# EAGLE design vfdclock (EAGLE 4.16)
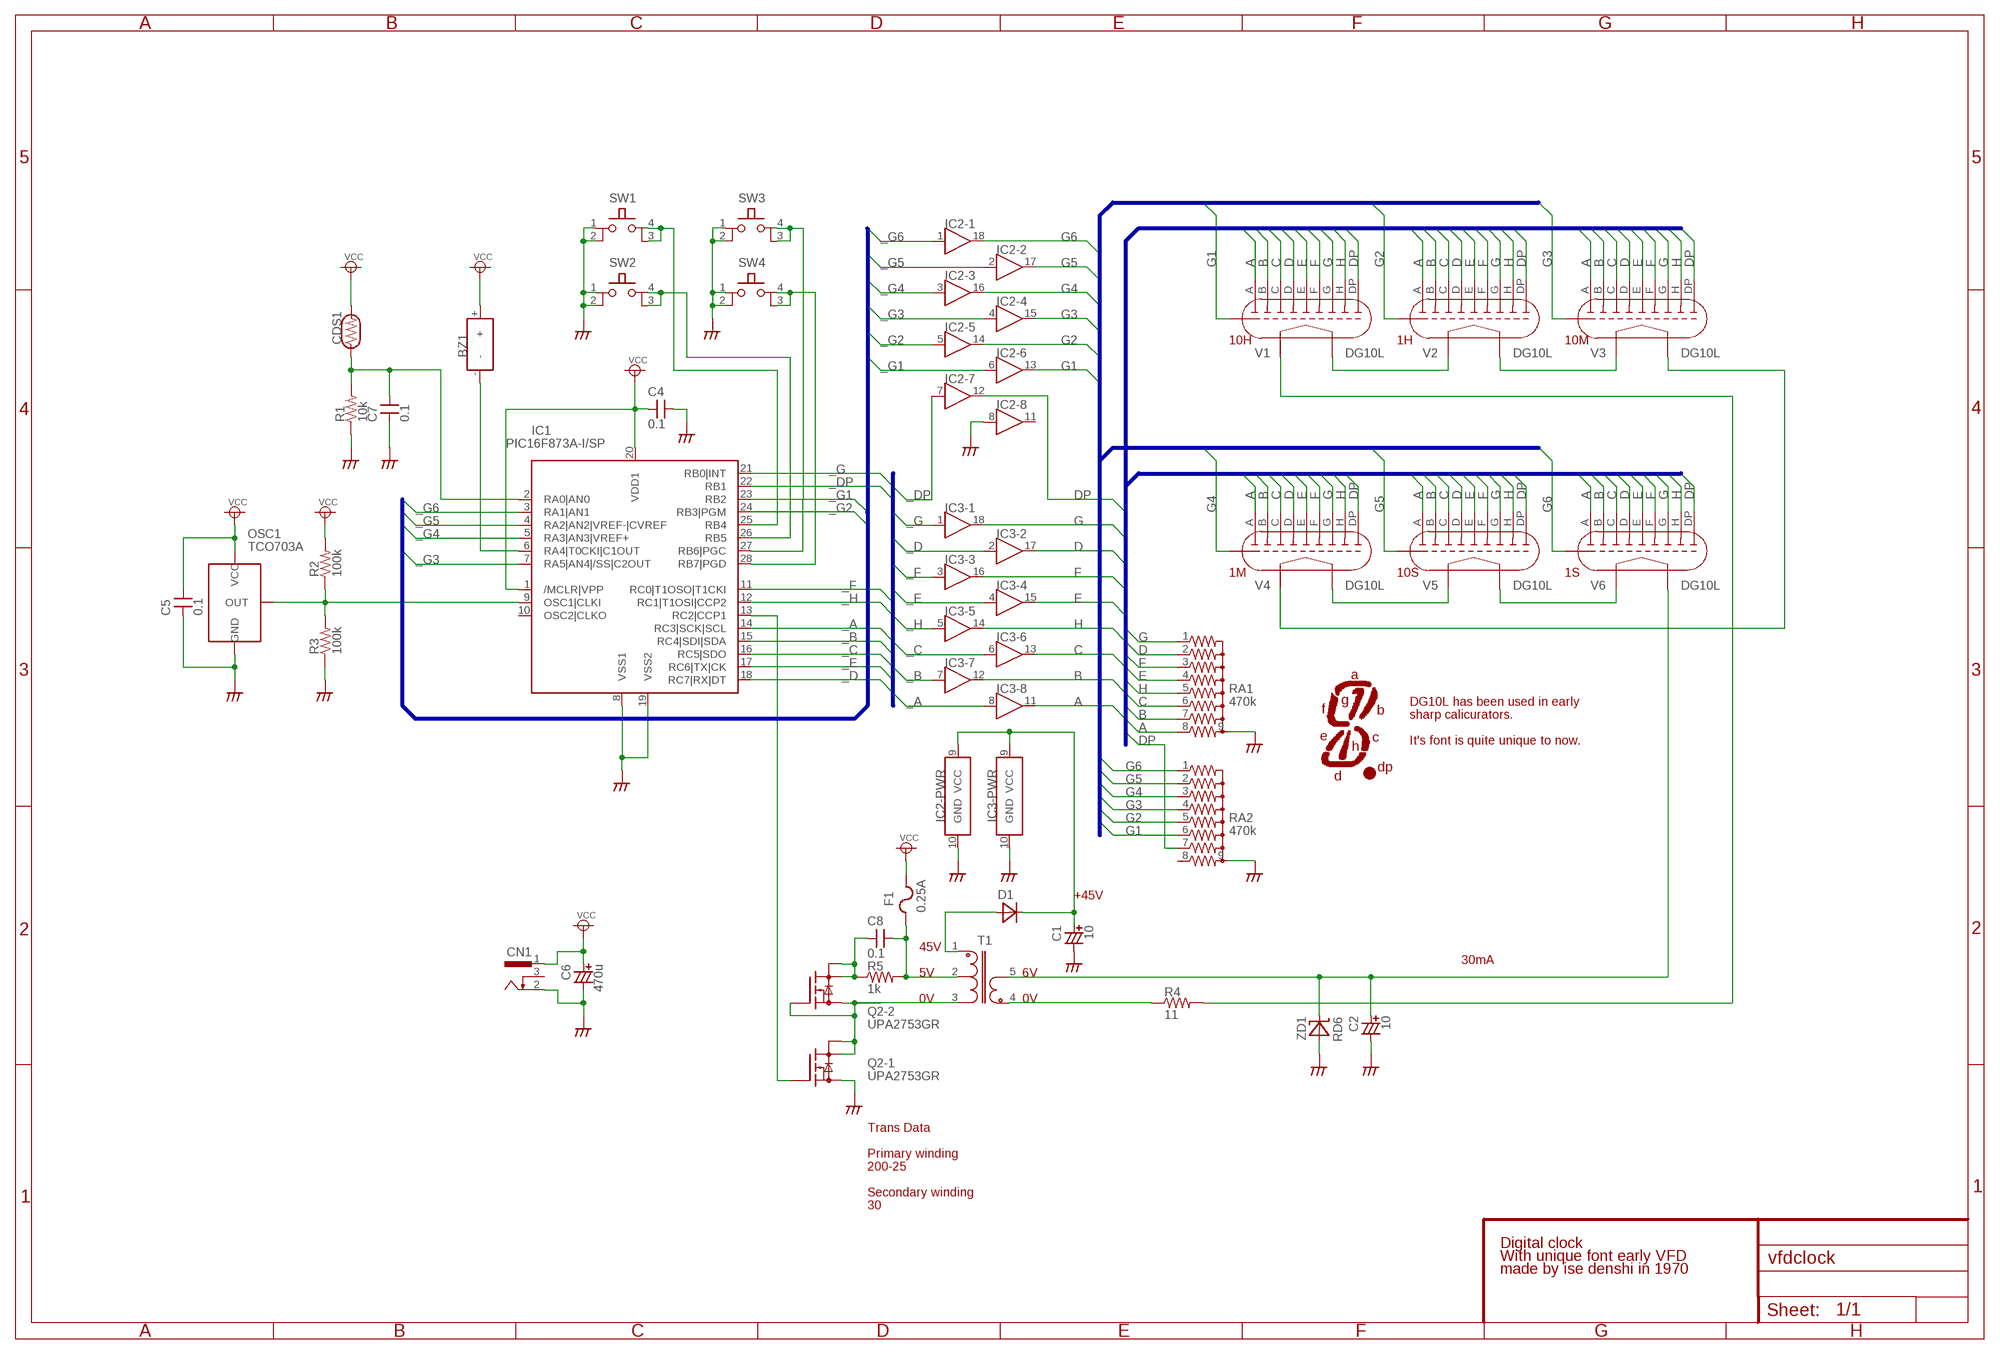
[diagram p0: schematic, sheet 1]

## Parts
BZ1  BUZZER  [HDB06LFPN]
C1  10  CCAP6.5  [CCAP_6.5]
C2  10  CCAP6.5  [CCAP_6.5]
C4  0.1  CAPDIP_2  [CAP_DIP_2]
C5  0.1  CAPDIP_2  [CAP_DIP_2]
C6  470u  CCAP8  [CCAP_8]
C7  0.1  CAPDIP_2  [CAP_DIP_2]
C8  0.1  CAPDIP_2  [CAP_DIP_2]
CDS1  CDS  [CDS_5MM]
CN1  DC-JACK2DC0005D100  [2DC0005D100]
D1  DIODEGENERIC_2  [DIODE_2]
F1  0.25A  POLYSW8X2MM  [AX_08X02_2P_200]
IC1  PIC16F873A-I/SP  [SOCKED-28-3]
IC2  TD62783AP  [SOCKED-18]
IC3  TD62783AP  [SOCKED-18]
OSC1  TCO703A  [TCO703A]
Q2  UPA2753GR  [SOP08]
R1  10k  R0.125W_2P  [R_0.125W_2]
R2  100k  R0.125W_2P  [R_0.125W_2]
R3  100k  R0.125W_2P  [R_0.125W_2]
R4  11  R0.125W_2P  [R_0.125W_2]
R5  1k  R0.125W_2P  [R_0.125W_2]
RA1  470k  R_ARRAY_8  [SIP9]
RA2  470k  R_ARRAY_8  [SIP9]
SW1  PUSHSW-6MM  [PUSHSW-6MM]
SW2  PUSHSW-6MM  [PUSHSW-6MM]
SW3  PUSHSW-6MM  [PUSHSW-6MM]
SW4  PUSHSW-6MM  [PUSHSW-6MM]
T1  TRANS  [TDK_BE16]
V1  DG10L  [DG10L]
V2  DG10L  [DG10L]
V3  DG10L  [DG10L]
V4  DG10L  [DG10L]
V5  DG10L  [DG10L]
V6  DG10L  [DG10L]
ZD1  RD6  ZENER_DIODE  [DIODE_2]

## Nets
_A: IC1.14(RC3|SCK|SCL) IC3.8(-8:IN)
_B: IC1.15(RC4|SDI|SDA) IC3.7(-7:IN)
_C: IC1.16(RC5|SDO) IC3.6(-6:IN)
_D: IC1.18(RC7|RX|DT) IC3.2(-2:IN)
_DP: IC1.22(RB1) IC2.7(-7:IN)
_E: IC1.17(RC6|TX|CK) IC3.4(-4:IN)
_F: IC1.11(RC0|T1OSO|T1CKI) IC3.3(-3:IN)
_G: IC1.21(RB0|INT) IC3.1(-1:IN)
_G1: IC1.23(RB2) IC2.6(-6:IN)
_G2: IC1.24(RB3|PGM) IC2.5(-5:IN)
_G3: IC1.7(RA5|AN4|/SS|C2OUT) IC2.4(-4:IN)
_G4: IC1.5(RA3|AN3|VREF+) IC2.3(-3:IN)
_G5: IC1.4(RA2|AN2|VREF-|CVREF) IC2.2(-2:IN)
_G6: IC1.3(RA1|AN1) IC2.1(-1:IN)
_H: IC1.12(RC1|T1OSI|CCP2) IC3.5(-5:IN)
A: IC3.11(-8:OUT) RA1.8 V1.A V2.A V3.A V4.A V5.A V6.A
B: IC3.12(-7:OUT) RA1.7 V1.B V2.B V3.B V4.B V5.B V6.B
C: IC3.13(-6:OUT) RA1.6 V1.C V2.C V3.C V4.C V5.C V6.C
D: IC3.17(-2:OUT) RA1.2 V1.D V2.D V3.D V4.D V5.D V6.D
DP: IC2.12(-7:OUT) RA2.7 V1.DP V2.DP V3.DP V4.DP V5.DP V6.DP
DVCC: BZ1.+ C4.1 C5.2 C6.+ CDS1.2 CN1.1 F1.2 IC1.1(/MCLR|VPP) IC1.20(VDD1) OSC1.VCC R2.2 ; supply symbol labelled VCC
E: IC3.15(-4:OUT) RA1.4 V1.E V2.E V3.E V4.E V5.E V6.E
F: IC3.16(-3:OUT) RA1.3 V1.F V2.F V3.F V4.F V5.F V6.F
F$1: V1.FL2 V2.FL1
F$2: V2.FL2 V3.FL1
F$3: V3.FL2 V4.FL1
F$4: V4.FL2 V5.FL1
F$5: V5.FL2 V6.FL1
FL1: R4.2 V1.FL1
FL2: C2.+ T1.5(S2) V6.FL2 ZD1.K
G: IC3.18(-1:OUT) RA1.1 V1.G V2.G V3.G V4.G V5.G V6.G
G1: IC2.13(-6:OUT) RA2.6 V1.GRID
G2: IC2.14(-5:OUT) RA2.5 V2.GRID
G3: IC2.15(-4:OUT) RA2.4 V3.GRID
G4: IC2.16(-3:OUT) RA2.3 V4.GRID
G5: IC2.17(-2:OUT) RA2.2 V5.GRID
G6: IC2.18(-1:OUT) RA2.1 V6.GRID
GND: C1.- C2.- C4.2 C5.1 C6.- C7.1 CN1.2 IC1.8(VSS1) IC1.19(VSS2) IC2.8(-8:IN) IC2.10(-PWR:GND) IC3.10(-PWR:GND) OSC1.GND Q2.1(-1:S) R1.1 R3.1 RA1.9(COM) RA2.9(COM) SW1.1 SW1.2 SW2.1 SW2.2 SW3.1 SW3.2 SW4.1 SW4.2 ZD1.A
H: IC3.14(-5:OUT) RA1.5 V1.H V2.H V3.H V4.H V5.H V6.H
N$1: IC1.13(RC2|CCP1) Q2.2(-1:G)
N$2: BZ1.- IC1.6(RA4|T0CKI|C1OUT)
N$3: R4.1 T1.4(S1)
N$4: C1.+ D1.K IC2.9(-PWR:VCC) IC3.9(-PWR:VCC)
N$5: IC1.25(RB4) SW1.3 SW1.4
N$6: IC1.26(RB5) SW2.3 SW2.4
N$7: C8.1 Q2.5(-2:D1) Q2.6(-2:D2) R5.1
N$8: C7.2 CDS1.1 IC1.2(RA0|AN0) R1.2
N$10: D1.A T1.1
N$13: IC1.9(OSC1|CLKI) OSC1.OUT R2.1 R3.2
N$14: C8.2 F1.1 R5.2 T1.2
N$15: Q2.3(-2:S) Q2.4(-2:G) Q2.7(-1:D1) Q2.8(-1:D2) T1.3
N$16: IC1.27(RB6|PGC) SW3.3 SW3.4
N$17: IC1.28(RB7|PGD) SW4.3 SW4.4
Unconnected: CN1.3 IC1.10(OSC2|CLKO) IC2.11(-8:OUT) RA2.8

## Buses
A,B,C,D,E,F,G,H,DP
G[1..6]
_A,_B,_C,_D,_E,_F,_G,_H,_DP
_G[1..6]

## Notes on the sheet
- 10H | 1H | 10M
- 1M | 10S | 1S
- a
- g | DG10L has been used in early
- f | b
- sharp calicurators.
- e | c
- It's font is quite unique to now.
- h
- dp
- d
- +45V
- 45V
- 30mA
- 5V | 6V
- 0V | 0V
- Trans Data
- Primary winding
- 200-25
- Secondary winding
- 30
- Digital clock
- With unique font early VFD
- made by ise denshi in 1970

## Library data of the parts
BZ1 = vfdclock:BUZZER
C1 C2 C6 = vfdclock:CCAP: Polar capacitor
C4 C5 C7 C8 = vfdclock:CAP: Non polar capacitor
CDS1 = vfdclock:CDS
CN1 = vfdclock:DC-JACK
D1 = vfdclock:DIODE
F1 = vfdclock:POLYSW
IC1 = vfdclock:PIC16F873
IC2 IC3 = vfdclock:TD62783
OSC1 = vfdclock:TCO703A
Q2 = vfdclock:UPA2753GR
R1-R5 = vfdclock:R
RA1 RA2 = vfdclock:R_ARRAY_8
SW1-SW4 = vfdclock:PUSHSW-6MM
T1 = vfdclock:TRANS
V1-V6 = vfdclock:DG10L: Early Vacuum Florescent Tube made by ISE denshi. It had unique font with 8 segments. Looks like hand-written number. Official specs are unknown but filament supply is about 0.6V/30mA
ZD1 = vfdclock:ZENER_DIODE

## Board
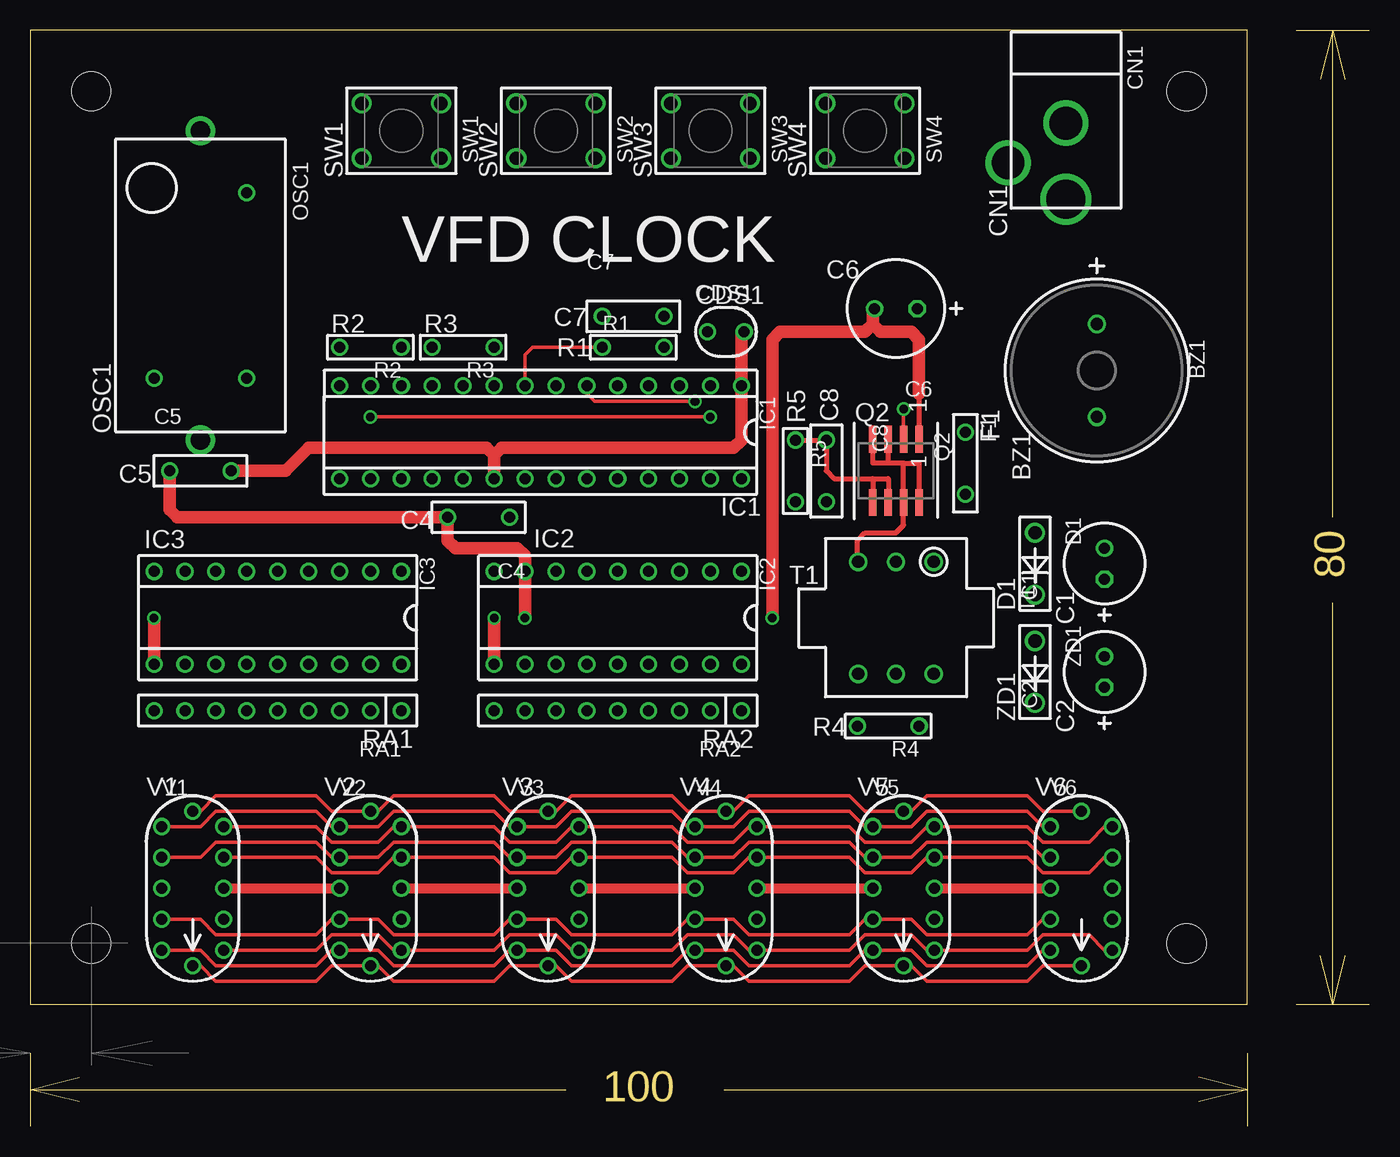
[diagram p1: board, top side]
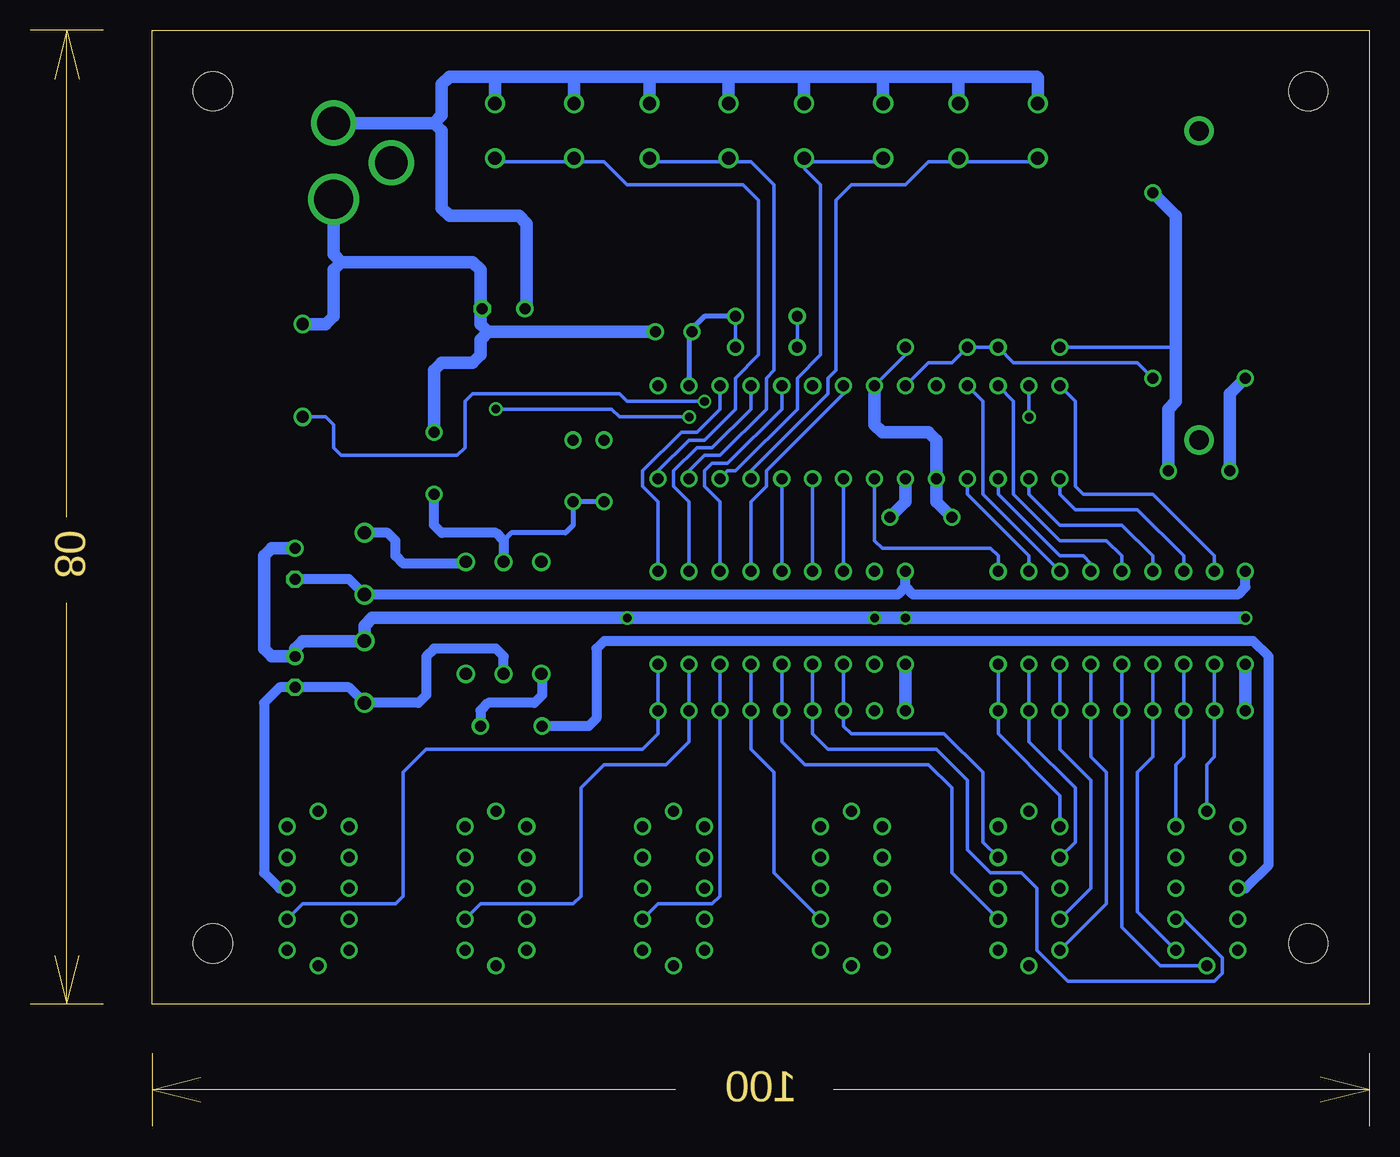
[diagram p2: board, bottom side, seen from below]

Size 110 x 90 mm. Coordinates in mm from the lower left corner, seen from the top.
Outline: 0,6 0,3
Outline: 0,3 0,0
Outline: 100,6 100,3
Outline: 100,3 100,0
Outline: 0,3 44,3
Outline: 57,3 100,3
Outline: 0,3 4,4
Outline: 4,2 0,3
Outline: 100,3 96,4
Outline: 100,3 96,2
Outline: 104,10 107,10
Outline: 107,10 110,10
Outline: 107,10 107,43
Outline: 107,50 107,90
Outline: 104,90 107,90
Outline: 107,90 110,90
Outline: 107,90 106,86
Outline: 107,90 108,86
Outline: 107,10 106,14
Outline: 108,14 107,10
Outline: 0,10 100,10 100,90 0,90 0,10
Copper layers (1*16): Top 0.035mm / dielectric 1.5mm / Bottom 0.035mm
Design rules "Olimex10mils": minimum track width 10mil, minimum drill 0.7mm, track to track 10mil, track to pad 10mil, pad to pad 10mil, via to via 10mil, smd to smd 10mil, copper to edge 40mil, drill to drill 10mil, minimum pad ring 10mil, minimum via ring 8mil, stop-mask expansion 0mil, vias tented up to drill 0mil, thermal gap 10mil
Holes 3.2 mm at 5,85 95,85 95,15 5,15

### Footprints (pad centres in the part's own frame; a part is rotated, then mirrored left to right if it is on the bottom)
HDB06LFPN = drill 1 round: + -3.81,0; - 3.81,0
CCAP_6.5 = drill 0.9 octagon: + -1.27,0 | drill 0.9 round: - 1.27,0
CAP_DIP_2 = drill 0.9 round: 1 -2.54,0; 2 2.54,0
CCAP_8 = drill 0.9 octagon: + -1.75,0 | drill 0.9 round: - 1.75,0
CDS_5MM = drill 0.9 round: 1 -1.5,0; 2 1.5,0
2DC0005D100 = drill 3.2 round: 1 6.25,0 | drill 2.7 round: 2 0,0; 3 3.25,-4.75
DIODE_2 = drill 1.1 round: A -2.54,0; K 2.54,0
AX_08X02_2P_200 = drill 0.9 round: 1 2.54,0; 2 -2.54,0
SOCKED-28-3 = drill 0.9 round: 1 -16.51,-3.81; 2 -13.97,-3.81; 3 -11.43,-3.81; 4 -8.89,-3.81; 5 -6.35,-3.81; 6 -3.81,-3.81; 7 -1.27,-3.81; 8 1.27,-3.81; 9 3.81,-3.81; 10 6.35,-3.81; 11 8.89,-3.81; 12 11.43,-3.81; 13 13.97,-3.81; 14 16.51,-3.81; 15 16.51,3.81; 16 13.97,3.81; 17 11.43,3.81; 18 8.89,3.81; 19 6.35,3.81; 20 3.81,3.81; 21 1.27,3.81; 22 -1.27,3.81; 23 -3.81,3.81; 24 -6.35,3.81; 25 -8.89,3.81; 26 -11.43,3.81; 27 -13.97,3.81; 28 -16.51,3.81
SOCKED-18 = drill 0.9 round: 1 -10.16,-3.81; 2 -7.62,-3.81; 3 -5.08,-3.81; 4 -2.54,-3.81; 5 0,-3.81; 6 2.54,-3.81; 7 5.08,-3.81; 8 7.62,-3.81; 9 10.16,-3.81; 10 10.16,3.81; 11 7.62,3.81; 12 5.08,3.81; 13 2.54,3.81; 14 0,3.81; 15 -2.54,3.81; 16 -5.08,3.81; 17 -7.62,3.81; 18 -10.16,3.81
TCO703A = drill 0.9 round: GND 7.62,-3.81; OUT 7.62,3.81; VCC -7.62,3.81 | drill 1.6 round: P$2 -12.7,0; P$3 12.7,0
SOP08 = smd 0.6 x 2.2: 1 -1.905,-2.6; 2 -0.635,-2.6; 3 0.635,-2.6; 4 1.905,-2.6; 5 1.905,2.6; 6 0.635,2.6; 7 -0.635,2.6; 8 -1.905,2.6
R_0.125W_2 = drill 0.9 round: 1 -2.54,0; 2 2.54,0
SIP9 = drill 0.9 round: 1 -10.16,0; 2 -7.62,0; 3 -5.08,0; 4 -2.54,0; 5 0,0; 6 2.54,0; 7 5.08,0; 8 7.62,0; 9 10.16,0
PUSHSW-6MM = drill 1.1 round: 1 -2.25,3.25; 2 -2.25,-3.25; 3 2.25,-3.25; 4 2.25,3.25
TDK_BE16 = drill 1 round: 1 -4.6,3.1; 2 -4.6,0; 3 -4.6,-3.1; 4 4.6,-3.1; 5 4.6,0; 6 4.6,3.1
DG10L = drill 0.9 round: A 0,6.35; B 2.54,5.08; C 2.54,-5.08; D -2.54,2.54; DP 2.54,2.54; E -2.54,-5.08; F -2.54,-2.54; FL1 -2.54,0; FL2 2.54,0; G -2.54,5.08; GRID 2.54,-2.54; H 0,-6.35

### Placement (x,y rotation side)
BZ1  87.63,62.07 270 top
C1  88.27,46.2 90 top
C2  88.27,37.3 90 top
C4  36.83,50.01 180 top
C5  13.97,53.81 0 top
C6  71.12,67.15 180 top
C7  49.53,66.52 0 top
C8  65.41,53.81 270 top
CDS1  57.15,65.25 0 top
CN1  85.09,82.39 270 top
D1  82.55,46.2 270 top
F1  76.83,54.45 270 top
IC1  41.91,56.99 180 top
IC2  48.26,41.75 180 top
IC3  20.32,41.75 180 top
OSC1  13.97,69.06 270 top
Q2  71.12,53.81 180 top
R1  49.53,63.98 0 top
R2  27.94,63.98 180 top
R3  35.56,63.98 180 top
R4  70.48,32.86 180 top
R5  62.87,53.81 270 top
RA1  20.32,34.13 180 top
RA2  48.26,34.13 180 top
SW1  30.48,81.75 270 top
SW2  43.18,81.75 270 top
SW3  55.88,81.75 270 top
SW4  68.58,81.75 270 top
T1  71.12,41.75 270 top
V1  13.34,19.52 0 top
V2  27.94,19.52 0 top
V3  42.55,19.52 0 top
V4  57.15,19.52 0 top
V5  71.75,19.52 0 top
V6  86.36,19.52 0 top
ZD1  82.55,37.3 270 top

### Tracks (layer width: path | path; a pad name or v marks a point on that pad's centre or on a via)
_A
  Bottom 0.305: IC3.8 12.7,46.83 17.78,51.91 23.5,51.91 24.13,52.55 24.13,59.53 IC1.14
_B
  Bottom 0.305: IC1.15 25.4,51.91 24.13,50.64 19.05,50.64 15.24,46.83 IC3.7
_C
  Bottom 0.305: IC1.16 27.94,51.91 25.4,49.37 20.32,49.37 17.78,46.83 IC3.6
_D
  Bottom 0.305: IC1.18 33.02,51.91 27.94,46.83 IC3.2
_DP
  Bottom 0.305: IC2.7 IC1.22
_E
  Bottom 0.305: IC1.17 30.48,51.91 25.4,46.83 23.5,46.83 22.86,46.2 IC3.4
_F
  Bottom 0.305: IC1.11 31.75,59.53 31.75,51.91 IC3.3
_G
  Bottom 0.305: IC1.21 40.64,48.1 40.01,47.47 31.11,47.47 30.48,46.83 IC3.1
_G1
  Bottom 0.305: IC2.6 IC1.23
_G2
  Bottom 0.305: IC2.5 IC1.24
_G3
  Bottom 0.305: IC1.7 43.18,60.16 49.53,53.81 49.53,52.55 50.8,51.27 IC2.4
_G4
  Bottom 0.305: IC1.5 48.26,58.9 52.7,54.45 53.98,54.45 54.61,53.81 54.61,52.55 53.34,51.27 IC2.3
_G5
  Bottom 0.305: IC1.4 50.8,58.9 53.98,55.72 55.24,55.72 57.15,53.81 57.15,52.55 55.88,51.27 IC2.2
_G6
  Bottom 0.305: IC1.3 53.34,58.9 55.24,56.99 56.52,56.99 59.69,53.81 59.69,52.55 58.42,51.27 IC2.1
_H
  Bottom 0.305: IC1.12 29.21,59.53 29.21,51.91 25.4,48.1 21.59,48.1 20.32,46.83 IC3.5
A
  Top 0.305: V1.A 13.97,25.88 15.24,27.14 23.5,27.14 24.77,25.88 V2.A 28.57,25.88 29.84,27.14 38.1,27.14 39.37,25.88 V3.A 43.18,25.88 44.45,27.14 52.7,27.14 53.98,25.88 V4.A 57.78,25.88 59.05,27.14 67.31,27.14 68.58,25.88 V5.A 72.39,25.88 73.66,27.14 81.92,27.14 83.19,25.88 V6.A
  Bottom 0.305: IC3.11 RA1.8 12.7,30.32 13.34,29.68 V1.A
B
  Top 0.305: V1.B 23.5,24.61 24.77,23.34 28.57,23.34 29.84,24.61 V2.B 38.1,24.61 39.37,23.34 43.18,23.34 44.45,24.61 V3.B 52.7,24.61 53.98,23.34 57.78,23.34 59.05,24.61 V4.B 67.31,24.61 68.58,23.34 72.39,23.34 73.66,24.61 V5.B 81.92,24.61 83.19,23.34 87,23.34 88.27,24.61 V6.B
  Bottom 0.305: IC3.12 RA1.7 15.24,30.32 15.88,29.68 V1.B
C
  Top 0.305: V1.C 23.5,14.45 24.77,15.71 28.57,15.71 29.84,14.45 V2.C 38.1,14.45 39.37,15.71 43.18,15.71 44.45,14.45 V3.C 52.7,14.45 53.98,15.71 57.78,15.71 59.05,14.45 V4.C 67.31,14.45 68.58,15.71 72.39,15.71 73.66,14.45 V5.C 81.92,14.45 83.19,15.71 87,15.71 88.27,14.45 V6.C
  Bottom 0.305: IC3.13 RA1.6 17.78,30.32 19.05,29.05 19.05,17.62 V1.C
D
  Top 0.305: V1.D 13.97,22.06 15.24,23.34 23.5,23.34 24.77,22.06 V2.D 28.57,22.06 29.84,23.34 38.1,23.34 39.37,22.06 V3.D 43.18,22.06 44.45,23.34 52.7,23.34 53.98,22.06 V4.D 57.78,22.06 59.05,23.34 67.31,23.34 68.58,22.06 V5.D 72.39,22.06 73.66,23.34 81.92,23.34 83.19,22.06 V6.D
  Bottom 0.305: IC3.17 RA1.2 27.94,31.59 24.13,27.78 24.13,23.34 V2.D
DP
  Top 0.305: V1.DP 23.5,22.06 24.77,20.8 28.57,20.8 29.84,22.06 V2.DP 38.1,22.06 39.37,20.8 43.18,20.8 44.45,22.06 V3.DP 52.7,22.06 53.98,20.8 57.78,20.8 59.05,22.06 V4.DP 67.31,22.06 68.58,20.8 72.39,20.8 73.66,22.06 V5.DP 81.92,22.06 83.19,20.8 87,20.8 88.27,22.06 V6.DP
  Bottom 0.305: IC2.12 RA2.7 43.18,32.86 42.55,32.23 34.92,32.23 31.75,29.05 31.75,23.34 V2.DP
DVCC
  Top 1.016: 38.1,55.09 38.73,55.72 57.78,55.72 58.42,56.35 IC1.1 58.42,65.25 CDS1.2 | 38.1,55.09 IC1.20 | 38.1,55.09 37.47,55.72 22.86,55.72 20.95,53.81 C5.2
  Bottom 0.305: 15.88,63.98 R2.2
  Bottom 1.016: IC1.20 38.1,51.27 C4.1 | CN1.1 85.09,71.59 84.45,70.96 | 84.45,70.96 73.66,70.96 73.03,70.33 73.03,67.15 | F1.2 76.83,62.07 76.2,62.7 73.66,62.7 73.03,63.34 73.03,64.61 72.39,65.25 | 72.39,65.25 73.03,65.88 73.03,67.15 | 73.03,67.15 C6.+ | CDS1.2 72.39,65.25 | OSC1.VCC 15.88,74.77 15.88,63.98 15.88,59.53 16.51,58.9 C5.2 | 84.45,70.96 85.09,70.33 85.09,66.52 85.72,65.88 BZ1.+
E
  Top 0.305: V1.E 13.97,14.45 15.24,13.18 23.5,13.18 24.77,14.45 V2.E 28.57,14.45 29.84,13.18 38.1,13.18 39.37,14.45 V3.E 43.18,14.45 44.45,13.18 52.7,13.18 53.98,14.45 V4.E 57.78,14.45 59.05,13.18 67.31,13.18 68.58,14.45 V5.E 72.39,14.45 73.66,13.18 81.92,13.18 83.19,14.45 V6.E
  Bottom 0.305: IC3.15 RA1.4 22.86,30.32 21.59,29.05 21.59,18.26 V2.E
F
  Top 0.305: V1.F 13.97,16.98 15.24,15.71 23.5,15.71 24.77,16.98 V2.F 28.57,16.98 29.84,15.71 38.1,15.71 39.37,16.98 V3.F 43.18,16.98 44.45,15.71 52.7,15.71 53.98,16.98 V4.F 57.78,16.98 59.05,15.71 67.31,15.71 68.58,16.98 V5.F 72.39,16.98 73.66,15.71 81.92,15.71 83.19,16.98 V6.F
  Bottom 0.305: IC3.16 RA1.3 25.4,30.95 22.86,28.41 22.86,19.52 V2.F
F$1
  Top 0.813: V1.FL2 V2.FL1
F$2
  Top 0.813: V2.FL2 V3.FL1
F$3
  Top 0.813: V3.FL2 V4.FL1
F$4
  Top 0.813: V4.FL2 V5.FL1
F$5
  Top 0.813: V5.FL2 V6.FL1
FL1
  Bottom 0.813: V1.FL1 10.16,19.52 8.26,21.43 8.26,38.58 9.53,39.84 62.87,39.84 63.5,39.21 63.5,33.5 64.14,32.86 R4.2
FL2
  Bottom 0.813: T1.5 71.12,38.58 71.75,39.21 76.83,39.21 77.47,38.58 77.47,35.4 78.11,34.77 ZD1.K 83.82,36.03 C2.+ 89.53,36.03 90.81,34.77 90.81,20.8 89.53,19.52 V6.FL2
G
  Top 0.305: V1.G 13.97,24.61 15.24,25.88 23.5,25.88 24.77,24.61 V2.G 28.57,24.61 29.84,25.88 38.1,25.88 39.37,24.61 V3.G 43.18,24.61 44.45,25.88 52.7,25.88 53.98,24.61 V4.G 57.78,24.61 59.05,25.88 67.31,25.88 68.58,24.61 V5.G 72.39,24.61 73.66,25.88 81.92,25.88 83.19,24.61 V6.G
  Bottom 0.305: IC3.18 RA1.1 30.48,32.23 25.4,27.14 V2.G
G1
  Bottom 0.305: IC2.13 RA2.6 45.72,32.23 44.45,30.95 35.56,30.95 33.02,28.41 33.02,22.7 31.11,20.8 28.57,20.8 27.3,19.52 27.3,14.45 24.77,11.9 12.7,11.9 12.06,12.54 12.06,13.81 15.24,16.98 V1.GRID
G2
  Bottom 0.305: IC2.14 RA2.5 48.26,31.59 46.35,29.68 36.2,29.68 34.29,27.78 34.29,20.8 V2.GRID
G3
  Bottom 0.305: IC2.15 RA2.4 50.8,30.95 48.9,29.05 48.9,20.8 V3.GRID
G4
  Bottom 0.305: IC2.16 RA2.3 53.34,18.89 53.98,18.26 58.42,18.26 V4.GRID
G5
  Bottom 0.305: IC2.17 RA2.2 55.88,31.59 57.78,29.68 62.87,29.68 64.77,27.78 64.77,18.89 65.41,18.26 73.03,18.26 V5.GRID
G6
  Bottom 0.305: IC2.18 RA2.1 58.42,32.23 59.69,30.95 77.47,30.95 79.38,29.05 79.38,18.89 80.01,18.26 87.63,18.26 V6.GRID
GND  (via drill 0.7)
  Top 0.305: R1.1 41.27,63.98 40.64,63.34 IC1.8
  Top 0.406: 73.03,56.35 Q2.1 73.03,60.16
  Top 1.016: v40.64,41.75 IC2.8 40.64,46.83 40.01,47.47 34.92,47.47 34.29,48.1 C4.2 12.06,50.01 11.43,50.64 C5.1 | v38.1,41.75 IC2.10 | IC3.10 v10.16,41.75 | 69.22,65.88 69.85,65.25 72.39,65.25 73.03,64.61 73.03,60.16 | C6.- 69.22,67.15 69.22,65.88 | v60.96,41.75 60.96,64.61 61.59,65.25 68.58,65.25 69.22,65.88
  Bottom 0.305: R1.1 C7.1 | R3.1 38.1,63.34 IC1.8
  Bottom 1.016: C4.2 35.56,51.27 IC1.19 35.56,56.35 36.2,56.99 40.01,56.99 40.64,57.62 IC1.8 | RA1.9 IC3.10 | IC2.10 RA2.9 | v10.16,41.75 v38.1,41.75 v40.64,41.75 v60.96,41.75 81.92,41.75 82.55,41.11 ZD1.A 87.63,39.84 88.27,39.21 C2.- 90.17,38.58 90.81,39.21 90.81,46.83 90.17,47.47 C1.- | 76.83,82.39 CN1.2 | 76.83,82.39 76.2,81.75 76.2,75.41 75.56,74.77 69.85,74.77 69.22,74.14 69.22,67.15 C6.- | 71.75,86.2 75.56,86.2 76.2,85.56 76.2,83.03 76.83,82.39 | 71.75,86.2 65.41,86.2 | 65.41,86.2 59.05,86.2 | 59.05,86.2 52.7,86.2 | 52.7,86.2 46.35,86.2 | 46.35,86.2 40.01,86.2 | 40.01,86.2 33.66,86.2 | 33.66,86.2 27.3,86.2 27.23,86.12 SW1.2 | SW4.1 71.83,86.12 71.75,86.2 | SW4.2 65.33,86.12 65.41,86.2 | SW3.1 59.13,86.12 59.05,86.2 | SW3.2 52.63,86.12 52.7,86.2 | SW2.1 46.43,86.12 46.35,86.2 | SW2.2 39.93,86.12 40.01,86.2 | SW1.1 33.73,86.12 33.66,86.2 | C5.1 11.43,60.16 OSC1.GND
H
  Top 0.305: V1.H 13.97,13.18 15.24,11.9 23.5,11.9 24.77,13.18 V2.H 28.57,13.18 29.84,11.9 38.1,11.9 39.37,13.18 V3.H 43.18,13.18 44.45,11.9 52.7,11.9 53.98,13.18 V4.H 57.78,13.18 59.05,11.9 67.31,11.9 68.58,13.18 V5.H 72.39,13.18 73.66,11.9 81.92,11.9 83.19,13.18 V6.H
  Bottom 0.305: IC3.14 RA1.5 20.32,16.35 17.14,13.18 V1.H
N$1  (via drill 0.7)
  Top 0.305: v27.94,58.26 v55.88,58.26 | 71.75,56.35 Q2.2 v71.75,58.9
  Bottom 0.305: v27.94,58.26 IC1.13 | v55.88,58.26 61.59,58.26 62.23,58.9 v71.75,58.9
N$2  (via drill 0.7)
  Top 0.305: v54.61,59.53 46.35,59.53 45.72,60.16 IC1.6
  Bottom 0.305: v54.61,59.53 60.96,59.53 61.59,60.16 73.66,60.16 74.3,59.53 74.3,55.72 74.93,55.09 84.45,55.09 85.09,55.72 85.09,57.62 85.72,58.26 BZ1.-
N$3
  Bottom 0.813: R4.1 73.03,34.13 72.39,34.77 68.58,34.77 67.94,35.4 67.94,37.3 68.02,37.23 T1.4
N$4
  Bottom 0.813: IC3.9 10.16,44.29 10.79,43.66 37.47,43.66 38.1,44.29 | 38.1,44.29 IC2.9 | 38.1,44.29 38.73,43.66 D1.K 83.82,44.92 C1.+
N$5
  Bottom 0.305: SW1.3 27.23,79.29 27.3,79.22 33.66,79.22 | 33.66,79.22 33.73,79.29 SW1.4 | 33.66,79.22 36.2,79.22 38.1,77.31 42.55,77.31 43.81,76.04 43.81,62.07 44.45,61.44 44.45,60.16 50.8,53.81 IC1.25
N$6
  Bottom 0.305: SW2.3 39.93,79.29 40.01,79.22 46.35,79.22 | 46.35,79.22 46.35,78.58 45.09,77.31 45.09,63.34 46.99,61.44 46.99,58.9 52.07,53.81 52.7,53.81 IC1.26 | 46.35,79.22 46.43,79.29 SW2.4
N$7
  Top 0.406: Q2.6 70.48,53.18 69.22,53.18 | 69.22,53.18 Q2.5 | R5.1 C8.1 65.41,53.81 66.04,53.18 69.22,53.18
N$8
  Bottom 0.305: R1.2 C7.2
  Bottom 0.406: 55.88,65.25 IC1.2 | 55.88,65.25 CDS1.1 | C7.2 54.61,66.52 55.88,65.25
N$10
  Bottom 0.813: D1.A 80.64,48.73 80.01,48.1 80.01,46.83 79.38,46.2 74.3,46.2 74.22,46.27 T1.1
N$13
  Bottom 0.305: OSC1.OUT 19.05,62.7 29.21,62.7 R2.1 R3.2 34.29,62.7 36.2,62.7 IC1.9
N$14
  Bottom 0.406: 71.12,48.1 70.48,48.73 66.04,48.73 65.41,49.37 C8.2 R5.2
  Bottom 0.813: 71.12,46.2 T1.2 71.12,48.1 71.75,48.73 76.2,48.73 76.83,49.37 F1.1
N$15
  Top 0.406: Q2.4 69.22,54.45 70.48,54.45 | 71.75,54.45 Q2.7 71.75,49.37 71.12,48.73 68.58,48.73 67.94,48.1 67.94,46.2 68.02,46.27 T1.3 | Q2.8 73.03,54.45 71.75,54.45 | 70.48,54.45 Q2.3 | 71.75,54.45 70.48,54.45
N$16
  Bottom 0.305: 52.7,79.22 59.05,79.22 59.13,79.29 SW3.4 | 52.7,79.22 52.63,79.29 SW3.3 | 52.7,79.22 50.8,79.22 48.9,77.31 48.9,62.07 49.53,61.44 49.53,58.9 53.34,55.09 54.61,55.09 55.88,53.81 IC1.27
N$17
  Bottom 0.305: 65.41,79.22 71.75,79.22 71.83,79.29 SW4.4 | 65.41,79.22 65.33,79.29 SW4.3 | 65.41,79.22 62.87,79.22 60.96,77.31 51.44,77.31 50.16,76.04 50.16,63.34 52.07,61.44 52.07,58.9 54.61,56.35 55.88,56.35 58.42,53.81 IC1.28

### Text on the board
Dimension: 80 | 100
tDocu: 5 | 5
_tPlace: SW1 | SW2 | SW3 | SW4 | VFD CLOCK | 1
_tNames: CN1 | C6 | CDS1 | R2 | R3 | C7 | R1 | OSC1 | R5 | C8 | F1 | Q2 | BZ1 | C5 | IC1 | C4 | IC3 | IC2 | T1 | D1 | C1 | R4 | RA1 | RA2 | ZD1 | C2 | V1 | V2 | V3 | V4 | V5 | V6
